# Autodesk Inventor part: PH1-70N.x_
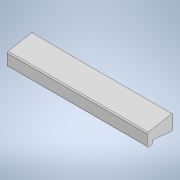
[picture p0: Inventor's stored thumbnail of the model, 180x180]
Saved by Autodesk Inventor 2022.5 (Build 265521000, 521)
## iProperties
Created: 2023-07
Part Number: PH1-70N.x_
Material: Generic
Document SubType Name: Modeling
Designer: ImaoCorp
Density: 1 g/cm^3
Appearance: Default
Sending System: SOLIDWORKS 2021-2021301
MC: AMD64
MC_MODEL: Intel64 Family 6 Model 60 Stepping 3, GenuineIntel
OS: Windows_NT
FRU: Parasolid Version 32.1, build 255,  1- 1-2021
FORMAT: text
GUISE: transmit
KEY: PH1-70N
FILE: PH1-70N.x_t
DATE: Tue Jul 25 09:28:44 2023
Author: ImaoCorp
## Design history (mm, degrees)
feature "Base1"
node "ソリッド1"
